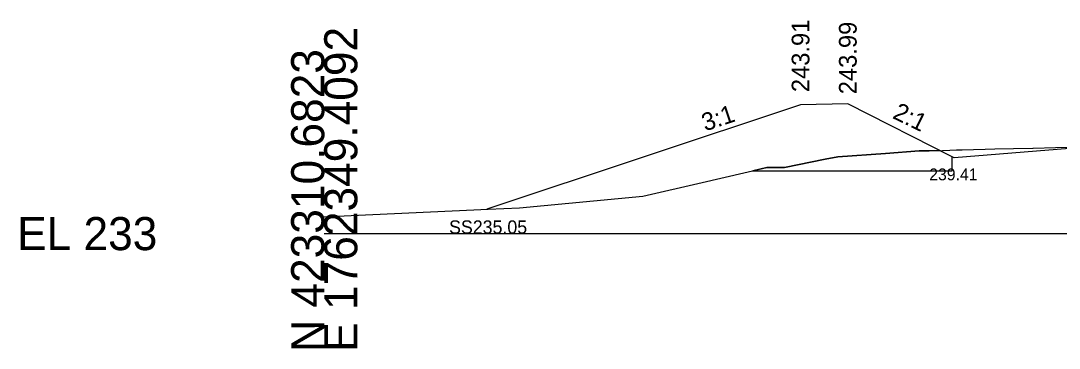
# Model space of a CAD drawing. Extents: x -26 to 3203, y -11010 to 4024.
# Drawn here: x -25.7 to 62.2, y 1990.3 to 2018 of the extents above; entities that cross this region are included whole.
import ezdxf

# ---------------------------------------------------------------- set-up
doc = ezdxf.new("R2010")
doc.units = 0
for name, color, linetype in [('Default', 7, 'Continuous'), ('Exist Cross Section Cell', 7, 'Continuous'), ('Exist XS Ground Line', 7, 'Continuous'), ('Prop CMT Slope Grass', 7, 'Continuous'), ('Prop CMT Undercut', 7, 'Continuous'), ('Prop CMT Undercut Boundary', 7, 'Continuous'), ('Prop XS Hydro Elevations', 7, 'Continuous'), ('Prop XS Side Slope Text', 7, 'Continuous'), ('Prop XS SS Elevation Text', 7, 'Continuous'), ('Scratch_Level_0', 7, 'Continuous')]:
    doc.layers.add(name, color=color, linetype=linetype)

msp = doc.modelspace()

# ---------------------------------------------------------------- linework, layer by layer
at = {"layer": 'Exist Cross Section Cell'}
msp.add_line((0, 2000), (100, 2000), dxfattribs=at)
at = {"layer": 'Exist XS Ground Line'}
msp.add_lwpolyline([(0, 2001.422), (0.774, 2001.458), (1.056, 2001.471), (13.88, 2002.059), (16.526, 2002.18), (26.986, 2003.168), (31.997, 2004.314), (37.478, 2005.583), (38.956, 2005.58), (42.405, 2006.297), (43.475, 2006.489), (47.515, 2006.789), (50.363, 2007.001), (50.96, 2007.003), (51.204, 2007.005), (52.33, 2007.039), (52.951, 2007.057), (53.518, 2007.073), (54.014, 2007.089), (54.967, 2007.119), (55.944, 2007.143), (56.773, 2007.162), (58.341, 2007.189), (59.986, 2007.237), (60.001, 2007.237), (60.021, 2007.237), (61.915, 2007.282), (63.275, 2007.309)], dxfattribs=at)
msp.add_lwpolyline([(0, 2001.422), (0.774, 2001.458), (1.056, 2001.471), (13.88, 2002.059), (16.526, 2002.18), (26.986, 2003.168), (31.997, 2004.314), (37.478, 2005.583), (38.956, 2005.58), (42.405, 2006.297), (43.475, 2006.489), (47.515, 2006.789), (50.363, 2007.001), (50.96, 2007.003), (51.204, 2007.005), (52.33, 2007.039), (52.951, 2007.057), (53.518, 2007.073), (54.014, 2007.089), (54.967, 2007.119), (55.944, 2007.143), (56.773, 2007.162), (58.341, 2007.189), (59.986, 2007.237), (60.001, 2007.237), (60.021, 2007.237), (61.915, 2007.282), (63.275, 2007.309)], dxfattribs=at)
msp.add_lwpolyline([(0, 2001.422), (0.774, 2001.458), (1.056, 2001.471), (13.88, 2002.059), (16.526, 2002.18), (26.986, 2003.168), (31.997, 2004.314), (37.478, 2005.583), (38.956, 2005.58), (42.405, 2006.297), (43.475, 2006.489), (47.515, 2006.789), (50.363, 2007.001), (50.96, 2007.003), (51.204, 2007.005), (52.33, 2007.039), (52.951, 2007.057), (53.518, 2007.073), (54.014, 2007.089), (54.967, 2007.119), (55.944, 2007.143), (56.773, 2007.162), (58.341, 2007.189), (59.986, 2007.237), (60.001, 2007.237), (60.021, 2007.237), (61.915, 2007.282), (63.275, 2007.309)], dxfattribs=at)
msp.add_lwpolyline([(0, 2001.422), (0.774, 2001.458), (1.056, 2001.471), (13.88, 2002.059), (16.526, 2002.18), (26.986, 2003.168), (31.997, 2004.314), (37.478, 2005.583), (38.956, 2005.58), (42.405, 2006.297), (43.475, 2006.489), (47.515, 2006.789), (50.363, 2007.001), (50.96, 2007.003), (51.204, 2007.005), (52.33, 2007.039), (52.951, 2007.057), (53.518, 2007.073), (54.014, 2007.089), (54.967, 2007.119), (55.944, 2007.143), (56.773, 2007.162), (58.341, 2007.189), (59.986, 2007.237), (60.001, 2007.237), (60.021, 2007.237), (61.915, 2007.282), (63.275, 2007.309)], dxfattribs=at)
msp.add_lwpolyline([(0, 2001.422), (0.774, 2001.458), (1.056, 2001.471), (13.88, 2002.059), (16.526, 2002.18), (26.986, 2003.168), (31.997, 2004.314), (37.478, 2005.583), (38.956, 2005.58), (42.405, 2006.297), (43.475, 2006.489), (47.515, 2006.789), (50.363, 2007.001), (50.96, 2007.003), (51.204, 2007.005), (52.33, 2007.039), (52.951, 2007.057), (53.518, 2007.073), (54.014, 2007.089), (54.967, 2007.119), (55.944, 2007.143), (56.773, 2007.162), (58.341, 2007.189), (59.986, 2007.237), (60.001, 2007.237), (60.021, 2007.237), (61.915, 2007.282), (63.275, 2007.309)], dxfattribs=at)
at = {"layer": 'Prop CMT Slope Grass'}
msp.add_lwpolyline([(65.175, 2007.354), (57.176, 2006.714), (53.326, 2006.406), (44.326, 2010.986), (40.326, 2010.906), (13.773, 2002.054)], dxfattribs=at)
at = {"layer": 'Prop CMT Undercut'}
msp.add_lwpolyline([(36.292, 2005.308), (53.171, 2005.308), (53.171, 2006.485), (52.096, 2007.032), (51.204, 2007.005), (50.363, 2007.001), (47.515, 2006.789), (43.475, 2006.489), (42.405, 2006.297), (38.956, 2005.58), (37.478, 2005.583)], close=True, dxfattribs=at)
at = {"layer": 'Prop CMT Undercut Boundary'}
msp.add_lwpolyline([(36.292, 2005.308), (53.171, 2005.308), (53.171, 2006.485), (52.096, 2007.032), (51.204, 2007.005), (50.363, 2007.001), (47.515, 2006.789), (43.475, 2006.489), (42.405, 2006.297), (38.956, 2005.58), (37.478, 2005.583), (36.292, 2005.308)], dxfattribs=at)

# ---------------------------------------------------------------- texts
at = {"layer": 'Default'}
msp.add_text('-', height=0.0001, dxfattribs=at).set_placement((0, 2000))
msp.add_text('-', height=0.0001, dxfattribs=at).set_placement((0, 2000))
at = {"layer": 'Exist Cross Section Cell'}
for s, p in [('E 1762349.4092', (2.8, 1990)), ('N 423310.6823', (0, 1990))]:
    msp.add_text(s, height=2.8, rotation=90, dxfattribs=at).set_placement(p)
msp.add_text('EL 233', height=2.8, dxfattribs=at).set_placement((-26, 1998.6))
at = {"layer": 'Prop XS Hydro Elevations'}
for s, p in [('243.91', (41.076, 2011.963)), ('243.99', (45.076, 2011.786))]:
    msp.add_text(s, height=1.5, rotation=90, dxfattribs=at).set_placement(p)
at = {"layer": 'Prop XS Side Slope Text'}
for s, rotation, p in [('3:1', 18.43493, (32.247, 2008.638)), ('2:1', 334.09695, (48.037, 2009.797))]:
    msp.add_text(s, height=1.5, rotation=rotation, dxfattribs=at).set_placement(p)
at = {"layer": 'Prop XS SS Elevation Text'}
for s, height, p in [('239.41', 1.0001, (51.217, 2004.509)), ('SS235.05', 1.125, (10.569, 1999.992))]:
    msp.add_text(s, height=height, dxfattribs=at).set_placement(p)
at = {"layer": 'Scratch_Level_0'}
for s, p in [('LT_Berm_Top out', (40.185, 2010.896)), ('LT_Berm_Top in', (44.201, 2010.976)), ('LT_Ditch_Bot', (53.222, 2006.396)), ('LT_GS_OS_CTL', (57.071, 2006.704)), ('Exterior Boundary', (13.614, 2002.044)), ('LT_Slope_Fill', (13.678, 2002.044))]:
    msp.add_text(s, height=0.02, dxfattribs=at).set_placement(p)

doc.saveas('drawing.dxf')
